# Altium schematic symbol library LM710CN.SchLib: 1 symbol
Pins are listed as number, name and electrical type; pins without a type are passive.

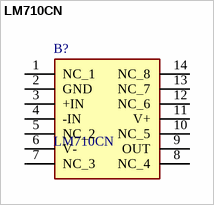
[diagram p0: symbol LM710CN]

## LM710CN
designator B?
Analog Comparators; Manufacturer_Name: Texas Instruments; Geometry.Height: 5.08mm
footprint DIP787W58P254L1918H508Q14N
pins: 1 NC_1, 2 GND, 3 +IN, 4 -IN, 5 NC_2, 6 V-, 7 NC_3, 8 NC_4, 9 OUT, 10 NC_5, 11 V+, 12 NC_6, 13 NC_7, 14 NC_8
